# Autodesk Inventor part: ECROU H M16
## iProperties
Created: 2004-11
Part Number: ECROU H M16
Document SubType Name: Modeling
Designer: Bruno
Manufacturer: Standard
Standards Organization: Custom
Author: Bruno
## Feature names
1. Base1
